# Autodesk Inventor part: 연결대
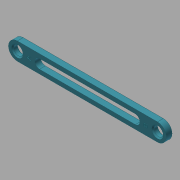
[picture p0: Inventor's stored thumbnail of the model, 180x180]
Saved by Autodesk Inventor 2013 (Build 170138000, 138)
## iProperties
Created: 2017-07
Part Number: 연결대
Material: 스테인리스강
Document SubType Name: Modeling
Designer: mduedu
Density: 8.08 g/cm^3
Mass: 46.8511 g
Surface Area: 49.3916 cm^2
Volume: 5.79841 cm^3
Author: mduedu
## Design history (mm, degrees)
sketch "스케치1"
  geometry: L1 (-67.5, 0)-(67.5, 0); L2 (-67.5, -7.5)-(67.5, -7.5); L3 (67.5, -7.5)-(67.5, 7.5); L4 (67.5, 7.5)-(-67.5, 7.5); L5 (-67.5, 7.5)-(-67.5, -7.5); L6 (-67.5, -7.5)-(67.5, 7.5); L7 (67.5, -7.5)-(-67.5, 7.5); 2 further points
  constraints: 14 end point, 4 midpoint, 2 horizontal, 2 parallel, 1 coincident, 1 perpendicular
  dimensions: "d0" = 135 distance of L1.start L1.end; "d2" = 15 distance of L2.end L3.end
extrude "돌출1" new body sketch "스케치1" distance "d3" = 5; taper "d4" = 0 deg
fillet "모깎기1"
fillet "모깎기2"
sketch "스케치2"
  geometry: C1 r 4 at (60, 0); A1 r 7.5 centre (60, 0) between (60, -7.5) and (60, 7.5) reference; 1 further point
  constraints: 1 centre point, 1 coincident
  dimensions: "d5" = 8 diameter of C1
extrude "돌출2" cut sketch "스케치2" stored distance "d6" = 10; taper "d7" = 0 deg
chamfer "모따기1" distance "d8" = 1; stored, may be unused: second distance "d9" = 2, angle "d10" = 45 deg
sketch "스케치3"
  geometry: L1 (-45, 0)-(45, 0); L2 (-45, -4)-(45, -4); L3 (45, -4)-(45, 4); L4 (45, 4)-(-45, 4); L5 (-45, 4)-(-45, -4); L6 (-45, -4)-(45, 4); L7 (45, -4)-(-45, 4); 2 further points
  constraints: 14 end point, 4 midpoint, 2 horizontal, 2 parallel, 1 coincident, 1 perpendicular
  dimensions: "d11" = 90 distance of L1.start L1.end; "d13" = 8 distance of L2.end L3.end
extrude "돌출3" cut sketch "스케치3" stored distance "d14" = 10; taper "d15" = 0 deg
fillet "모깎기3"
fillet "모깎기4"
sketch "스케치4"
  geometry: L1 (-60, 0)-(60, 0); C1 r 5 at (-60, 0) reference; C2 r 5 at (60, 0) reference; 3 further points
  constraints: 2 end point, 2 point on line, 1 horizontal, 2 other
  dimensions: "d16" = 50 distance of point (-50, 0) point (0, 0); "d17" = 50 distance of point (50, 0) point (0, 0)
feature "엠보싱1" sketch "스케치4" dims "d0" = 135, "d2" = 15, "d18" = 0.5, "d19" = 0
node "솔리드1"
mirror "대칭1"
